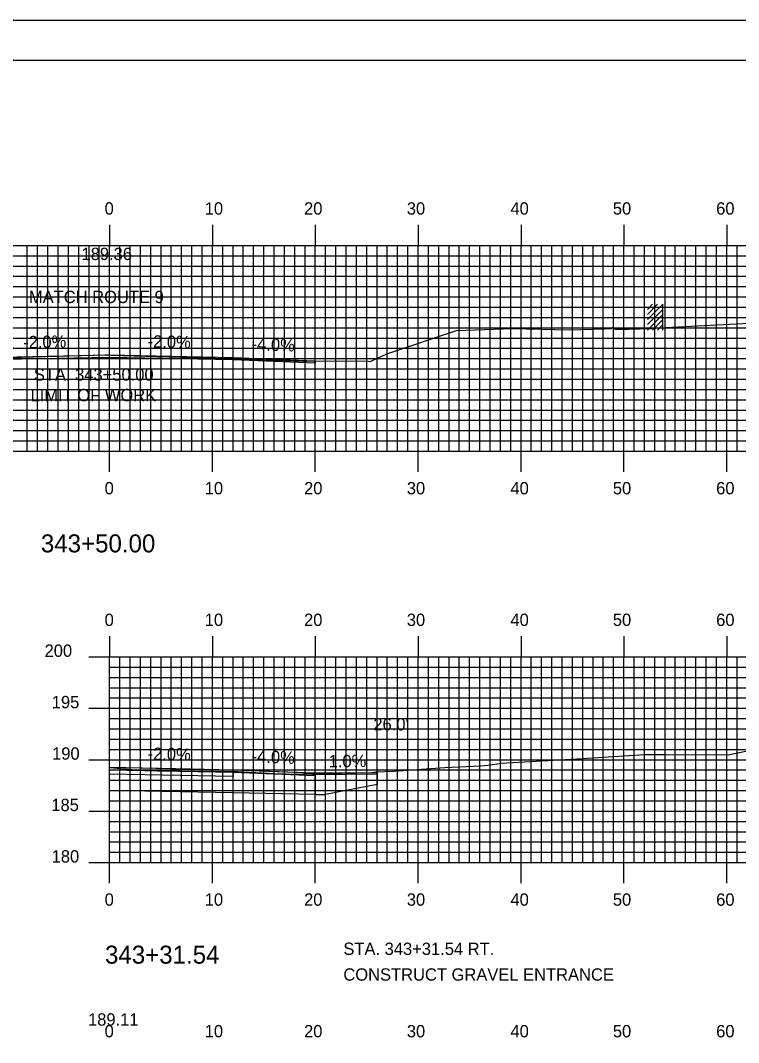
# Model space of a CAD drawing. Extents: x 1825147 to 1825490, y 442591 to 442811.
# Drawn here: x 1825303.7 to 1825373.5, y 442711.2 to 442810.5 of the extents above; entities that cross this region are included whole.
import ezdxf

# ---------------------------------------------------------------- set-up
doc = ezdxf.new("R2010")
doc.units = 0
for name, color, linetype in [('ANNOTATION', 7, 'Continuous'), ('BORDER', 7, 'Continuous'), ('D_Roadway_Centerline', 7, 'Continuous'), ('D_Roadway_Centerline_Text', 7, 'Continuous'), ('D_Roadway_Edge_Shoulder', 7, 'Continuous'), ('D_Roadway_Edge_TW', 7, 'Continuous'), ('D_Roadway_Pavement', 7, 'Continuous'), ('D_Roadway_SubGrade', 7, 'Continuous'), ('D_Text_Standard', 7, 'Continuous'), ('H_V ANNOTATION', 7, 'Continuous'), ('M_Buildings_Rooftop', 7, 'Continuous'), ('MAJOR', 7, 'Continuous'), ('MINOR', 7, 'Continuous'), ('PLOT BOUNDARY', 7, 'Continuous'), ('S_Roadway_Centerline', 7, 'Continuous')]:
    doc.layers.add(name, color=color, linetype=linetype)

msp = doc.modelspace()

# ---------------------------------------------------------------- linework, layer by layer
at = {"layer": 'BORDER'}
msp.add_lwpolyline([(1825162.761, 442596.665), (1825482.761, 442596.665), (1825482.761, 442806.665), (1825162.761, 442806.665)], close=True, dxfattribs=at)
at = {"layer": 'D_Roadway_Centerline'}
for points in [[(1825312.361, 442737.93), (1825318.806, 442737.802), (1825324.361, 442737.69), (1825328.657, 442737.519), (1825332.361, 442737.37)], [(1825312.361, 442737.93), (1825324.361, 442737.69), (1825332.361, 442737.37)], [(1825312.361, 442737.93), (1825324.361, 442737.69), (1825332.361, 442737.37)]]:
    msp.add_lwpolyline(points, dxfattribs=at)
at = {"layer": 'D_Roadway_Edge_Shoulder'}
for points in [[(1825324.361, 442777.783), (1825332.361, 442777.463), (1825332.361, 442777.213), (1825324.361, 442777.533)], [(1825324.361, 442737.69), (1825332.361, 442737.37), (1825332.361, 442737.12), (1825324.361, 442737.44)], [(1825324.361, 442737.69), (1825332.361, 442737.37), (1825332.361, 442737.12), (1825324.361, 442737.44)]]:
    msp.add_lwpolyline(points, close=True, dxfattribs=at)
at = {"layer": 'D_Roadway_Edge_TW'}
msp.add_lwpolyline([(1825300.361, 442777.533), (1825300.361, 442777.783), (1825312.361, 442778.023), (1825324.361, 442777.783), (1825324.361, 442777.533), (1825312.361, 442777.773)], close=True, dxfattribs=at)
at = {"layer": 'D_Roadway_Pavement'}
msp.add_lwpolyline([(1825312.361, 442737.68), (1825324.361, 442737.44), (1825324.361, 442737.024), (1825312.361, 442737.264)], dxfattribs=at)
at = {"layer": 'D_Roadway_SubGrade'}
for p, q in [((1825332.361, 442737.37), (1825338.361, 442737.427)), ((1825338.361, 442737.261), (1825332.378, 442737.202)), ((1825338.361, 442737.427), (1825338.361, 442736.261)), ((1825338.361, 442737.427), (1825338.361, 442737.261)), ((1825338.361, 442736.261), (1825333.361, 442735.28)), ((1825332.361, 442735.28), (1825333.361, 442735.28))]:
    msp.add_line(p, q, dxfattribs=at)
msp.add_lwpolyline([(1825312.361, 442737.68), (1825324.361, 442737.44), (1825332.361, 442737.12), (1825332.361, 442737.37), (1825332.361, 442735.28), (1825324.361, 442735.44), (1825312.361, 442735.68)], dxfattribs=at)
at = {"layer": 'M_Buildings_Rooftop'}
for p, q in [((1825364.652, 442781.457), (1825366.161, 442782.966)), ((1825364.652, 442781.949), (1825365.636, 442782.966)), ((1825364.652, 442782.441), (1825365.144, 442782.966)), ((1825366.161, 442780.44), (1825366.161, 442782.966)), ((1825364.652, 442780.965), (1825366.161, 442782.441)), ((1825364.652, 442780.44), (1825366.161, 442781.949)), ((1825365.144, 442780.44), (1825366.161, 442781.457)), ((1825365.636, 442780.44), (1825366.161, 442780.965))]:
    msp.add_line(p, q, dxfattribs=at)
at = {"layer": 'MAJOR'}
for p, q in [((1825312.361, 442790.669), (1825312.361, 442788.665)), ((1825322.361, 442790.669), (1825322.361, 442788.665)), ((1825332.361, 442790.669), (1825332.361, 442788.665)), ((1825342.361, 442790.669), (1825342.361, 442788.665)), ((1825352.361, 442790.669), (1825352.361, 442788.665)), ((1825362.361, 442790.669), (1825362.361, 442788.665)), ((1825372.361, 442790.669), (1825372.361, 442788.665)), ((1825172.361, 442788.665), (1825452.361, 442788.665)), ((1825172.361, 442788.665), (1825452.361, 442788.665)), ((1825312.361, 442768.665), (1825312.361, 442788.665)), ((1825322.361, 442768.665), (1825322.361, 442788.665)), ((1825332.361, 442768.665), (1825332.361, 442788.665)), ((1825342.361, 442768.665), (1825342.361, 442788.665)), ((1825352.361, 442768.665), (1825352.361, 442788.665)), ((1825362.361, 442768.665), (1825362.361, 442788.665)), ((1825372.361, 442768.665), (1825372.361, 442788.665)), ((1825172.361, 442783.665), (1825452.361, 442783.665)), ((1825172.361, 442778.665), (1825452.361, 442778.665)), ((1825172.361, 442773.665), (1825452.361, 442773.665)), ((1825172.361, 442768.665), (1825452.361, 442768.665)), ((1825172.361, 442768.665), (1825452.361, 442768.665)), ((1825312.361, 442766.661), (1825312.361, 442768.665)), ((1825322.361, 442766.661), (1825322.361, 442768.665)), ((1825332.361, 442766.661), (1825332.361, 442768.665)), ((1825342.361, 442766.661), (1825342.361, 442768.665)), ((1825352.361, 442766.661), (1825352.361, 442768.665)), ((1825362.361, 442766.661), (1825362.361, 442768.665)), ((1825372.361, 442766.661), (1825372.361, 442768.665)), ((1825312.361, 442750.669), (1825312.361, 442748.665)), ((1825322.361, 442750.669), (1825322.361, 442748.665)), ((1825332.361, 442750.669), (1825332.361, 442748.665)), ((1825342.361, 442750.669), (1825342.361, 442748.665)), ((1825352.361, 442750.669), (1825352.361, 442748.665)), ((1825362.361, 442750.669), (1825362.361, 442748.665)), ((1825372.361, 442750.669), (1825372.361, 442748.665)), ((1825310.357, 442748.665), (1825312.361, 442748.665)), ((1825312.361, 442748.665), (1825452.361, 442748.665)), ((1825312.361, 442728.665), (1825312.361, 442748.665)), ((1825312.361, 442728.665), (1825312.361, 442748.665)), ((1825312.361, 442748.665), (1825452.361, 442748.665)), ((1825322.361, 442728.665), (1825322.361, 442748.665)), ((1825332.361, 442728.665), (1825332.361, 442748.665)), ((1825342.361, 442728.665), (1825342.361, 442748.665)), ((1825352.361, 442728.665), (1825352.361, 442748.665)), ((1825362.361, 442728.665), (1825362.361, 442748.665)), ((1825372.361, 442728.665), (1825372.361, 442748.665)), ((1825310.357, 442743.665), (1825312.361, 442743.665)), ((1825312.361, 442743.665), (1825452.361, 442743.665)), ((1825310.357, 442738.665), (1825312.361, 442738.665)), ((1825312.361, 442738.665), (1825452.361, 442738.665)), ((1825310.357, 442733.665), (1825312.361, 442733.665)), ((1825312.361, 442733.665), (1825452.361, 442733.665)), ((1825310.357, 442728.665), (1825312.361, 442728.665)), ((1825312.361, 442728.665), (1825452.361, 442728.665)), ((1825312.361, 442728.665), (1825452.361, 442728.665)), ((1825312.361, 442726.661), (1825312.361, 442728.665)), ((1825322.361, 442726.661), (1825322.361, 442728.665)), ((1825332.361, 442726.661), (1825332.361, 442728.665)), ((1825342.361, 442726.661), (1825342.361, 442728.665)), ((1825352.361, 442726.661), (1825352.361, 442728.665)), ((1825362.361, 442726.661), (1825362.361, 442728.665)), ((1825372.361, 442726.661), (1825372.361, 442728.665))]:
    msp.add_line(p, q, dxfattribs=at)
at = {"layer": 'MINOR'}
for p, q in [((1825304.361, 442768.665), (1825304.361, 442788.665)), ((1825305.361, 442768.665), (1825305.361, 442788.665)), ((1825306.361, 442768.665), (1825306.361, 442788.665)), ((1825307.361, 442768.665), (1825307.361, 442788.665)), ((1825308.361, 442768.665), (1825308.361, 442788.665)), ((1825309.361, 442768.665), (1825309.361, 442788.665)), ((1825310.361, 442768.665), (1825310.361, 442788.665)), ((1825311.361, 442768.665), (1825311.361, 442788.665)), ((1825313.361, 442768.665), (1825313.361, 442788.665)), ((1825314.361, 442768.665), (1825314.361, 442788.665)), ((1825315.361, 442768.665), (1825315.361, 442788.665)), ((1825316.361, 442768.665), (1825316.361, 442788.665)), ((1825317.361, 442768.665), (1825317.361, 442788.665)), ((1825318.361, 442768.665), (1825318.361, 442788.665)), ((1825319.361, 442768.665), (1825319.361, 442788.665)), ((1825320.361, 442768.665), (1825320.361, 442788.665)), ((1825321.361, 442768.665), (1825321.361, 442788.665)), ((1825323.361, 442768.665), (1825323.361, 442788.665)), ((1825324.361, 442768.665), (1825324.361, 442788.665)), ((1825325.361, 442768.665), (1825325.361, 442788.665)), ((1825326.361, 442768.665), (1825326.361, 442788.665)), ((1825327.361, 442768.665), (1825327.361, 442788.665)), ((1825328.361, 442768.665), (1825328.361, 442788.665)), ((1825329.361, 442768.665), (1825329.361, 442788.665)), ((1825330.361, 442768.665), (1825330.361, 442788.665)), ((1825331.361, 442768.665), (1825331.361, 442788.665)), ((1825333.361, 442768.665), (1825333.361, 442788.665)), ((1825334.361, 442768.665), (1825334.361, 442788.665)), ((1825335.361, 442768.665), (1825335.361, 442788.665)), ((1825336.361, 442768.665), (1825336.361, 442788.665)), ((1825337.361, 442768.665), (1825337.361, 442788.665)), ((1825338.361, 442768.665), (1825338.361, 442788.665)), ((1825339.361, 442768.665), (1825339.361, 442788.665)), ((1825340.361, 442768.665), (1825340.361, 442788.665)), ((1825341.361, 442768.665), (1825341.361, 442788.665)), ((1825343.361, 442768.665), (1825343.361, 442788.665)), ((1825344.361, 442768.665), (1825344.361, 442788.665)), ((1825345.361, 442768.665), (1825345.361, 442788.665)), ((1825346.361, 442768.665), (1825346.361, 442788.665)), ((1825347.361, 442768.665), (1825347.361, 442788.665)), ((1825348.361, 442768.665), (1825348.361, 442788.665)), ((1825349.361, 442768.665), (1825349.361, 442788.665)), ((1825350.361, 442768.665), (1825350.361, 442788.665)), ((1825351.361, 442768.665), (1825351.361, 442788.665)), ((1825353.361, 442768.665), (1825353.361, 442788.665)), ((1825354.361, 442768.665), (1825354.361, 442788.665)), ((1825355.361, 442768.665), (1825355.361, 442788.665)), ((1825356.361, 442768.665), (1825356.361, 442788.665)), ((1825357.361, 442768.665), (1825357.361, 442788.665)), ((1825358.361, 442768.665), (1825358.361, 442788.665)), ((1825359.361, 442768.665), (1825359.361, 442788.665)), ((1825360.361, 442768.665), (1825360.361, 442788.665)), ((1825361.361, 442768.665), (1825361.361, 442788.665)), ((1825363.361, 442768.665), (1825363.361, 442788.665)), ((1825364.361, 442768.665), (1825364.361, 442788.665)), ((1825365.361, 442768.665), (1825365.361, 442788.665)), ((1825366.361, 442768.665), (1825366.361, 442788.665)), ((1825367.361, 442768.665), (1825367.361, 442788.665)), ((1825368.361, 442768.665), (1825368.361, 442788.665)), ((1825369.361, 442768.665), (1825369.361, 442788.665)), ((1825370.361, 442768.665), (1825370.361, 442788.665)), ((1825371.361, 442768.665), (1825371.361, 442788.665)), ((1825373.361, 442768.665), (1825373.361, 442788.665)), ((1825172.361, 442787.665), (1825452.361, 442787.665)), ((1825172.361, 442786.665), (1825452.361, 442786.665)), ((1825172.361, 442785.665), (1825452.361, 442785.665)), ((1825172.361, 442784.665), (1825452.361, 442784.665)), ((1825172.361, 442782.665), (1825452.361, 442782.665)), ((1825172.361, 442781.665), (1825452.361, 442781.665)), ((1825172.361, 442780.665), (1825452.361, 442780.665)), ((1825172.361, 442779.665), (1825452.361, 442779.665)), ((1825172.361, 442777.665), (1825452.361, 442777.665)), ((1825172.361, 442776.665), (1825452.361, 442776.665)), ((1825172.361, 442775.665), (1825452.361, 442775.665)), ((1825172.361, 442774.665), (1825452.361, 442774.665)), ((1825172.361, 442772.665), (1825452.361, 442772.665)), ((1825172.361, 442771.665), (1825452.361, 442771.665)), ((1825172.361, 442770.665), (1825452.361, 442770.665)), ((1825172.361, 442769.665), (1825452.361, 442769.665)), ((1825313.361, 442728.665), (1825313.361, 442748.665)), ((1825314.361, 442728.665), (1825314.361, 442748.665)), ((1825315.361, 442728.665), (1825315.361, 442748.665)), ((1825316.361, 442728.665), (1825316.361, 442748.665)), ((1825317.361, 442728.665), (1825317.361, 442748.665)), ((1825318.361, 442728.665), (1825318.361, 442748.665)), ((1825319.361, 442728.665), (1825319.361, 442748.665)), ((1825320.361, 442728.665), (1825320.361, 442748.665)), ((1825321.361, 442728.665), (1825321.361, 442748.665)), ((1825323.361, 442728.665), (1825323.361, 442748.665)), ((1825324.361, 442728.665), (1825324.361, 442748.665)), ((1825325.361, 442728.665), (1825325.361, 442748.665)), ((1825326.361, 442728.665), (1825326.361, 442748.665)), ((1825327.361, 442728.665), (1825327.361, 442748.665)), ((1825328.361, 442728.665), (1825328.361, 442748.665)), ((1825329.361, 442728.665), (1825329.361, 442748.665)), ((1825330.361, 442728.665), (1825330.361, 442748.665)), ((1825331.361, 442728.665), (1825331.361, 442748.665)), ((1825333.361, 442728.665), (1825333.361, 442748.665)), ((1825334.361, 442728.665), (1825334.361, 442748.665)), ((1825335.361, 442728.665), (1825335.361, 442748.665)), ((1825336.361, 442728.665), (1825336.361, 442748.665)), ((1825337.361, 442728.665), (1825337.361, 442748.665)), ((1825338.361, 442728.665), (1825338.361, 442748.665)), ((1825339.361, 442728.665), (1825339.361, 442748.665)), ((1825340.361, 442728.665), (1825340.361, 442748.665)), ((1825341.361, 442728.665), (1825341.361, 442748.665)), ((1825343.361, 442728.665), (1825343.361, 442748.665)), ((1825344.361, 442728.665), (1825344.361, 442748.665)), ((1825345.361, 442728.665), (1825345.361, 442748.665)), ((1825346.361, 442728.665), (1825346.361, 442748.665)), ((1825347.361, 442728.665), (1825347.361, 442748.665)), ((1825348.361, 442728.665), (1825348.361, 442748.665)), ((1825349.361, 442728.665), (1825349.361, 442748.665)), ((1825350.361, 442728.665), (1825350.361, 442748.665)), ((1825351.361, 442728.665), (1825351.361, 442748.665)), ((1825353.361, 442728.665), (1825353.361, 442748.665)), ((1825354.361, 442728.665), (1825354.361, 442748.665)), ((1825355.361, 442728.665), (1825355.361, 442748.665)), ((1825356.361, 442728.665), (1825356.361, 442748.665)), ((1825357.361, 442728.665), (1825357.361, 442748.665)), ((1825358.361, 442728.665), (1825358.361, 442748.665)), ((1825359.361, 442728.665), (1825359.361, 442748.665)), ((1825360.361, 442728.665), (1825360.361, 442748.665)), ((1825361.361, 442728.665), (1825361.361, 442748.665)), ((1825363.361, 442728.665), (1825363.361, 442748.665)), ((1825364.361, 442728.665), (1825364.361, 442748.665)), ((1825365.361, 442728.665), (1825365.361, 442748.665)), ((1825366.361, 442728.665), (1825366.361, 442748.665)), ((1825367.361, 442728.665), (1825367.361, 442748.665)), ((1825368.361, 442728.665), (1825368.361, 442748.665)), ((1825369.361, 442728.665), (1825369.361, 442748.665)), ((1825370.361, 442728.665), (1825370.361, 442748.665)), ((1825371.361, 442728.665), (1825371.361, 442748.665)), ((1825373.361, 442728.665), (1825373.361, 442748.665)), ((1825312.361, 442747.665), (1825452.361, 442747.665)), ((1825312.361, 442747.665), (1825314.365, 442747.665)), ((1825312.361, 442746.665), (1825452.361, 442746.665)), ((1825312.361, 442746.665), (1825314.365, 442746.665)), ((1825312.361, 442745.665), (1825452.361, 442745.665)), ((1825312.361, 442745.665), (1825314.365, 442745.665)), ((1825312.361, 442744.665), (1825452.361, 442744.665)), ((1825312.361, 442744.665), (1825314.365, 442744.665)), ((1825312.361, 442742.665), (1825452.361, 442742.665)), ((1825312.361, 442742.665), (1825314.365, 442742.665)), ((1825312.361, 442741.665), (1825452.361, 442741.665)), ((1825312.361, 442741.665), (1825314.365, 442741.665)), ((1825312.361, 442740.665), (1825452.361, 442740.665)), ((1825312.361, 442740.665), (1825314.365, 442740.665)), ((1825312.361, 442739.665), (1825452.361, 442739.665)), ((1825312.361, 442739.665), (1825314.365, 442739.665)), ((1825312.361, 442737.665), (1825452.361, 442737.665)), ((1825312.361, 442737.665), (1825314.365, 442737.665)), ((1825312.361, 442736.665), (1825452.361, 442736.665)), ((1825312.361, 442736.665), (1825314.365, 442736.665)), ((1825312.361, 442735.665), (1825452.361, 442735.665)), ((1825312.361, 442735.665), (1825314.365, 442735.665)), ((1825312.361, 442734.665), (1825452.361, 442734.665)), ((1825312.361, 442734.665), (1825314.365, 442734.665)), ((1825312.361, 442732.665), (1825452.361, 442732.665)), ((1825312.361, 442732.665), (1825314.365, 442732.665)), ((1825312.361, 442731.665), (1825452.361, 442731.665)), ((1825312.361, 442731.665), (1825314.365, 442731.665)), ((1825312.361, 442730.665), (1825452.361, 442730.665)), ((1825312.361, 442730.665), (1825314.365, 442730.665)), ((1825312.361, 442729.665), (1825452.361, 442729.665)), ((1825312.361, 442729.665), (1825314.365, 442729.665))]:
    msp.add_line(p, q, dxfattribs=at)
at = {"layer": 'PLOT BOUNDARY'}
msp.add_lwpolyline([(1825146.574, 442590.547), (1825486.574, 442590.547), (1825486.574, 442810.547), (1825146.574, 442810.547)], close=True, dxfattribs=at)
at = {"layer": 'S_Roadway_Centerline'}
for points in [[(1825299.11, 442777.683), (1825311.93, 442778.021), (1825312.234, 442778.033), (1825312.494, 442778.012), (1825323.791, 442777.661), (1825324.492, 442777.648), (1825324.775, 442777.649), (1825325.553, 442777.603), (1825331.225, 442777.41), (1825331.391, 442777.423), (1825331.48, 442777.418), (1825332.199, 442777.436), (1825334.676, 442777.4), (1825337.302, 442777.439), (1825337.715, 442777.38), (1825337.98, 442777.519), (1825339.317, 442778.128), (1825346.091, 442780.412), (1825351.517, 442780.584), (1825357.003, 442780.469), (1825360.493, 442780.564), (1825361.132, 442780.602), (1825361.279, 442780.735), (1825361.551, 442780.53), (1825362.808, 442780.513), (1825365.042, 442780.577), (1825365.462, 442780.618), (1825365.764, 442780.649), (1825375.793, 442781.166)], [(1825312.361, 442737.893), (1825312.377, 442737.894), (1825314.92, 442737.694), (1825317.021, 442737.586), (1825321.14, 442737.511), (1825324.797, 442737.517), (1825328.35, 442737.309), (1825330.703, 442737.264), (1825331.607, 442737.336), (1825331.972, 442737.313), (1825332.082, 442737.297), (1825333.644, 442737.302), (1825334.663, 442737.33), (1825334.926, 442737.351), (1825337.871, 442737.419), (1825338.288, 442737.477), (1825339.981, 442737.534), (1825344.967, 442737.915), (1825348.419, 442738.069), (1825349.119, 442738.144), (1825349.804, 442738.236), (1825350.425, 442738.31), (1825357.784, 442738.735), (1825364.387, 442739.162), (1825366.468, 442739.177), (1825372.498, 442739.152), (1825374.22, 442739.482)]]:
    msp.add_lwpolyline(points, dxfattribs=at)

# ---------------------------------------------------------------- texts
at = {"layer": 'ANNOTATION'}
for s, p in [('MATCH ROUTE 9', (1825304.52, 442783.064)), ('STA. 343+50.00', (1825304.998, 442775.52)), ('LIMIT OF WORK', (1825304.677, 442773.516))]:
    msp.add_text(s, height=1.2, dxfattribs=at).set_placement(p)
for s, rotation, p in [('-2.0%', 1.14576, (1825303.967, 442778.655)), ('-2.0%', 358.85424, (1825316.047, 442778.749)), ('-4.0%', 357.70939, (1825326.153, 442778.513)), ('-2.0%', 358.85424, (1825316.047, 442738.657)), ('-4.0%', 357.70939, (1825326.153, 442738.42)), ('1.0%', 0.54245, (1825333.665, 442737.917))]:
    msp.add_text(s, height=1.2, rotation=rotation, dxfattribs=at).set_placement(p)
at = {"layer": 'D_Roadway_Centerline'}
for s, p in [('C', (1825312.356, 442778.023)), ('L', (1825312.361, 442778.015))]:
    msp.add_text(s, height=0.0146, dxfattribs=at).set_placement(p)
at = {"layer": 'D_Roadway_Centerline_Text'}
for s, p in [('189.36', (1825309.632, 442787.25)), ('189.11', (1825310.264, 442712.803))]:
    msp.add_text(s, height=1.2, dxfattribs=at).set_placement(p)
at = {"layer": 'D_Text_Standard'}
for s, p in [("26.0'", (1825338.007, 442741.511)), ('STA. 343+31.54 RT.', (1825335.089, 442719.676)), ('CONSTRUCT GRAVEL ENTRANCE', (1825335.089, 442717.176))]:
    msp.add_text(s, height=1.2, dxfattribs=at).set_placement(p)
at = {"layer": 'H_V ANNOTATION'}
for s, height, p in [('0', 1.2, (1825311.879, 442791.665)), ('10', 1.2, (1825321.612, 442791.665)), ('20', 1.2, (1825331.269, 442791.665)), ('30', 1.2, (1825341.258, 442791.665)), ('40', 1.2, (1825351.333, 442791.665)), ('50', 1.2, (1825361.29, 442791.665)), ('60', 1.2, (1825371.333, 442791.665)), ('0', 1.2, (1825311.879, 442764.465)), ('10', 1.2, (1825321.612, 442764.465)), ('20', 1.2, (1825331.269, 442764.465)), ('30', 1.2, (1825341.258, 442764.465)), ('40', 1.2, (1825351.333, 442764.465)), ('50', 1.2, (1825361.29, 442764.465)), ('60', 1.2, (1825371.333, 442764.465)), ('343+50.00', 1.75, (1825305.682, 442758.821)), ('0', 1.2, (1825311.879, 442751.665)), ('10', 1.2, (1825321.612, 442751.665)), ('20', 1.2, (1825331.269, 442751.665)), ('30', 1.2, (1825341.258, 442751.665)), ('40', 1.2, (1825351.333, 442751.665)), ('50', 1.2, (1825361.29, 442751.665)), ('60', 1.2, (1825371.333, 442751.665)), ('200', 1.2, (1825306.042, 442748.665)), ('195', 1.2, (1825306.739, 442743.665)), ('190', 1.2, (1825306.771, 442738.665)), ('185', 1.2, (1825306.696, 442733.665)), ('180', 1.2, (1825306.728, 442728.665)), ('0', 1.2, (1825311.879, 442724.465)), ('10', 1.2, (1825321.612, 442724.465)), ('20', 1.2, (1825331.269, 442724.465)), ('30', 1.2, (1825341.258, 442724.465)), ('40', 1.2, (1825351.333, 442724.465)), ('50', 1.2, (1825361.29, 442724.465)), ('60', 1.2, (1825371.333, 442724.465)), ('343+31.54', 1.75, (1825311.916, 442718.831)), ('0', 1.2, (1825311.879, 442711.665)), ('10', 1.2, (1825321.612, 442711.665)), ('20', 1.2, (1825331.269, 442711.665)), ('30', 1.2, (1825341.258, 442711.665)), ('40', 1.2, (1825351.333, 442711.665)), ('50', 1.2, (1825361.29, 442711.665)), ('60', 1.2, (1825371.333, 442711.665))]:
    msp.add_text(s, height=height, dxfattribs=at).set_placement(p)
at = {"layer": 'MAJOR'}
msp.add_text('-', height=0.012, dxfattribs=at).set_placement((1825312.352, 442728.665))
at = {"layer": 'S_Roadway_Centerline'}
for s, p in [('L', (1825312.225, 442778.025)), ('C', (1825312.229, 442778.033))]:
    msp.add_text(s, height=0.0146, dxfattribs=at).set_placement(p)

doc.saveas('drawing.dxf')
